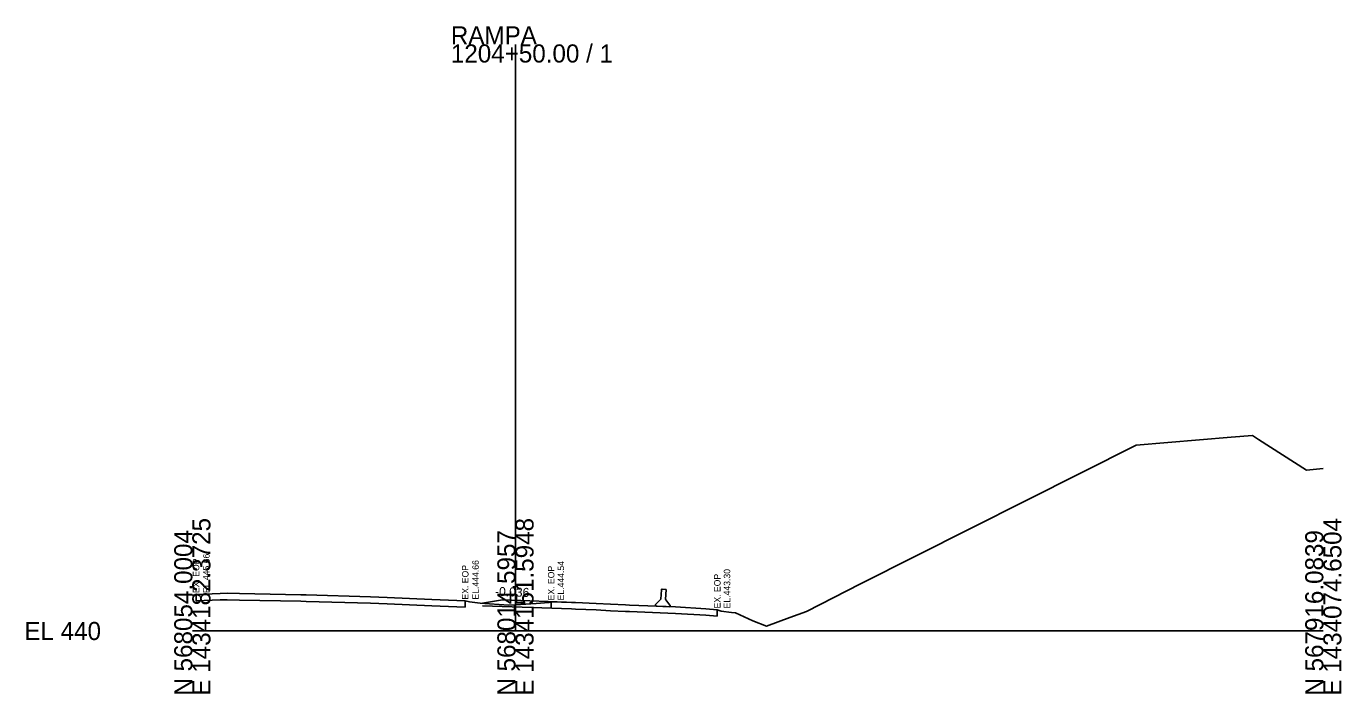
# Model space of a CAD drawing. Extents: x 1431908 to 1449087, y 567604 to 577825.
# Drawn here: x 1431908 to 1432111.5, y 575852.5 to 575955.7 of the extents above; entities that cross this region are included whole.
import ezdxf

# ---------------------------------------------------------------- set-up
doc = ezdxf.new("R2010")
doc.units = 0
for name, color, linetype in [('DESIGN - SHEET - Light Grid', 7, 'Continuous'), ('DESIGN - TYPICAL - Finished Grade and Subgrade', 7, 'Continuous'), ('SURVEY - GROUND - Existing Pavement Layer', 7, 'Continuous'), ('SURVEY - GROUND - Existing Pavement Text', 7, 'Continuous'), ('SURVEY - GROUND - Top of Ground', 7, 'Continuous')]:
    doc.layers.add(name, color=color, linetype=linetype)

msp = doc.modelspace()

# ---------------------------------------------------------------- linework, layer by layer
at = {"layer": 'DESIGN - SHEET - Light Grid'}
for p, q in [((1431983.66, 575862.16), (1431983.66, 575952.89)), ((1431933.66, 575862.16), (1431983.66, 575862.16)), ((1431983.66, 575862.16), (1432108.66, 575862.16))]:
    msp.add_line(p, q, dxfattribs=at)
at = {"layer": 'DESIGN - TYPICAL - Finished Grade and Subgrade'}
for p, q in [((1432005.37, 575866.31), (1432006.11, 575867.03)), ((1432006.14, 575867.09), (1432006.23, 575868.54)), ((1432006.34, 575868.63), (1432006.98, 575868.59)), ((1432006.89, 575867.05), (1432006.98, 575868.59)), ((1431981.66, 575866.96), (1431978.58, 575866.45)), ((1431981.66, 575866.96), (1431992.94, 575866.56)), ((1432005.33, 575866.13), (1432005.34, 575866.24)), ((1432005.42, 575866.02), (1432007.47, 575865.9)), ((1432007.56, 575866.17), (1432006.91, 575866.98)), ((1432007.58, 575865.99), (1432007.58, 575866.1))]:
    msp.add_line(p, q, dxfattribs=at)
for centre, start, end in [((1432006.04, 575867.1), 314.0314, 356.4785), ((1432006.33, 575868.53), 86.4785, 176.4785), ((1432006.99, 575867.04), 176.4785, 218.9256), ((1432005.43, 575866.12), 176.4785, 266.4785), ((1432005.44, 575866.24), 134.0314, 176.4785), ((1432007.48, 575866), 266.4785, 356.4785), ((1432007.48, 575866.11), 356.4785, 38.9256)]:
    msp.add_arc(centre, 0.1, start, end, dxfattribs=at)
at = {"layer": 'SURVEY - GROUND - Existing Pavement Layer'}
for p, q in [((1431934.23, 575866.82), (1431934.23, 575867.82)), ((1431934.23, 575866.82), (1431937.99, 575866.96)), ((1431937.99, 575866.96), (1431939.06, 575866.99)), ((1431939.06, 575866.99), (1431940.97, 575866.95)), ((1431940.97, 575866.95), (1431950.45, 575866.75)), ((1431950.45, 575866.75), (1431951.26, 575866.73)), ((1431951.26, 575866.73), (1431961.21, 575866.44)), ((1431961.21, 575866.44), (1431963.82, 575866.36)), ((1431963.82, 575866.36), (1431970.74, 575866.04)), ((1431970.74, 575866.04), (1431975.89, 575865.82)), ((1431975.89, 575866.82), (1431975.89, 575865.82)), ((1431978.57, 575866.07), (1431992.35, 575865.58)), ((1431989.18, 575865.69), (1431989.18, 575866.69)), ((1431992.35, 575865.58), (1431992.94, 575865.56)), ((1431992.94, 575865.56), (1431996.13, 575865.41)), ((1431996.13, 575865.41), (1431998.38, 575865.3)), ((1431998.38, 575865.3), (1432000.7, 575865.19)), ((1432000.7, 575865.19), (1432001.29, 575865.16)), ((1432001.29, 575865.16), (1432008.44, 575864.88)), ((1432014.89, 575865.45), (1432014.89, 575864.45)), ((1432008.44, 575864.88), (1432013.11, 575864.59)), ((1432013.11, 575864.59), (1432014.89, 575864.45))]:
    msp.add_line(p, q, dxfattribs=at)
at = {"layer": 'SURVEY - GROUND - Top of Ground'}
msp.add_lwpolyline([(1431933.66, 575867.72), (1431934.23, 575867.82), (1431937.99, 575867.96), (1431939.06, 575867.99), (1431940.97, 575867.95), (1431950.45, 575867.75), (1431951.26, 575867.73), (1431961.21, 575867.44), (1431963.82, 575867.36), (1431970.74, 575867.04), (1431975.89, 575866.82), (1431976.55, 575866.65), (1431978.22, 575866.48), (1431982.57, 575866.15), (1431983.66, 575866.22), (1431986.87, 575866.41), (1431988.8, 575866.59), (1431989.18, 575866.69), (1431992.35, 575866.58), (1431992.94, 575866.56), (1431996.13, 575866.41), (1431998.38, 575866.3), (1432000.7, 575866.19), (1432001.29, 575866.16), (1432008.44, 575865.88), (1432013.11, 575865.59), (1432014.89, 575865.45), (1432015.47, 575865.23), (1432017.1, 575865), (1432017.69, 575864.97), (1432020.4, 575863.74), (1432022.49, 575862.88), (1432026.09, 575864.23), (1432028.69, 575865.2), (1432037.07, 575869.44), (1432079.68, 575890.88), (1432094.42, 575892.14), (1432097.7, 575892.4), (1432098.64, 575891.8), (1432106.08, 575887.02), (1432108.66, 575887.31)], dxfattribs=at)

# ---------------------------------------------------------------- texts
at = {"layer": 'DESIGN - SHEET - Light Grid'}
for s, p in [('RAMPA', (1431973.66, 575952.89)), ('1204+50.00 / 1', (1431973.66, 575950.09)), ('EL 440', (1431907.66, 575860.76))]:
    msp.add_text(s, height=2.8, dxfattribs=at).set_placement(p)
for s, p in [('E 1434182.3725', (1431936.46, 575852.16)), ('E 1434151.5948', (1431986.46, 575852.16)), ('E 1434074.6504', (1432111.46, 575852.16)), ('N 568054.0004', (1431933.66, 575852.16)), ('N 568014.5957', (1431983.66, 575852.16)), ('N 567916.0839', (1432108.66, 575852.16))]:
    msp.add_text(s, height=2.8, rotation=90, dxfattribs=at).set_placement(p)
at = {"layer": 'DESIGN - TYPICAL - Finished Grade and Subgrade'}
msp.add_text('-0.036', height=1.4, rotation=357.955, dxfattribs=at).set_placement((1431980.47, 575867.6))
at = {"layer": 'SURVEY - GROUND - Existing Pavement Text'}
for s, p in [('EX. EOP', (1431934.73, 575868.02)), ('EL.445.66', (1431936.32, 575868.02)), ('EX. EOP', (1431976.39, 575867.02)), ('EL.444.66', (1431977.98, 575867.02)), ('EX. EOP', (1431989.68, 575866.89)), ('EL.444.54', (1431991.18, 575866.89)), ('EL.443.30', (1432016.89, 575865.65)), ('EX. EOP', (1432015.39, 575865.65))]:
    msp.add_text(s, height=1, rotation=90, dxfattribs=at).set_placement(p)

doc.saveas('drawing.dxf')
